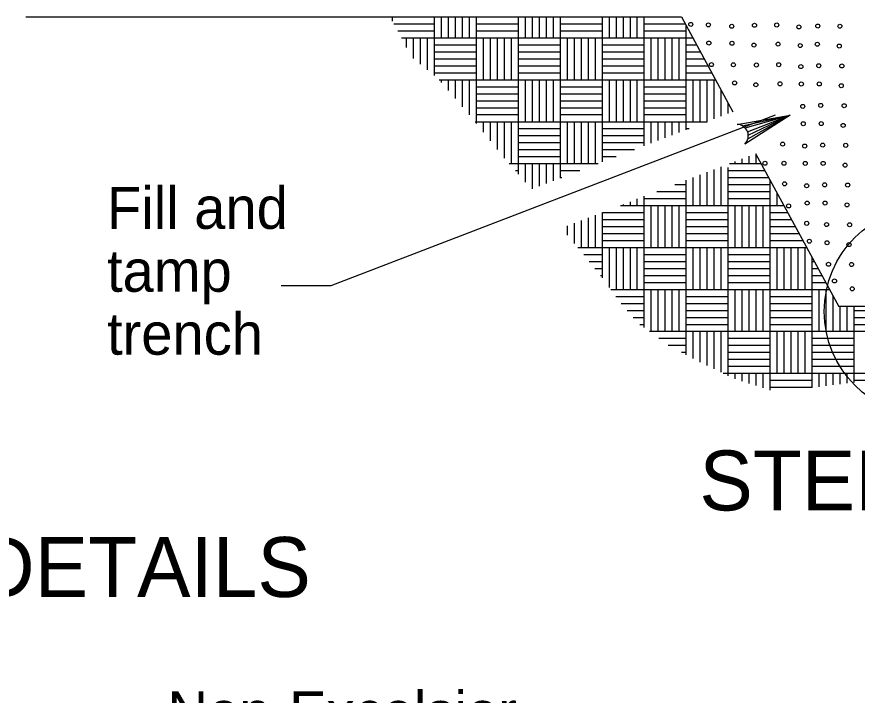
# Model space of a CAD drawing. Extents: x 1083.1 to 1117.1, y 719.4 to 741.4.
# Drawn here: x 1104.489 to 1107.293, y 732.693 to 734.956 of the extents above; entities that cross this region are included whole.
import ezdxf

# ---------------------------------------------------------------- set-up
doc = ezdxf.new("R2010")
doc.units = 0
doc.layers.add('ST_Details', color=7, linetype='Continuous')
doc.layers.add('ST_Text', color=7, linetype='Continuous')

msp = doc.modelspace()

# ---------------------------------------------------------------- linework, layer by layer
at = {"layer": 'ST_Details'}
for p, q in [((1104.5193, 734.9563), (1106.6565, 734.9563)), ((1105.7431, 734.9412), (1105.7431, 734.9563)), ((1105.7431, 734.9563), (1105.883, 734.9563)), ((1105.883, 734.7605), (1105.883, 734.9563)), ((1105.9064, 734.8863), (1105.9064, 734.9563)), ((1105.9297, 734.8863), (1105.9297, 734.9563)), ((1105.953, 734.8863), (1105.953, 734.9563)), ((1105.9764, 734.8863), (1105.9764, 734.9563)), ((1105.9997, 734.8863), (1105.9997, 734.9563)), ((1106.023, 734.6003), (1106.023, 734.9563)), ((1106.023, 734.9563), (1106.163, 734.9563)), ((1106.163, 734.4314), (1106.163, 734.9563)), ((1106.1863, 734.8863), (1106.1863, 734.9563)), ((1106.2095, 734.8863), (1106.2095, 734.9563)), ((1106.2329, 734.8863), (1106.2329, 734.9563)), ((1106.2562, 734.8863), (1106.2562, 734.9563)), ((1106.2795, 734.8863), (1106.2795, 734.9563)), ((1106.3029, 734.9563), (1106.4428, 734.9563)), ((1106.3029, 734.4184), (1106.3029, 734.9563)), ((1106.4428, 734.4721), (1106.4428, 734.9563)), ((1106.4661, 734.8863), (1106.4661, 734.9563)), ((1106.4895, 734.8863), (1106.4895, 734.9563)), ((1106.5128, 734.8863), (1106.5128, 734.9563)), ((1106.5361, 734.8863), (1106.5361, 734.9563)), ((1106.5594, 734.8863), (1106.5594, 734.9563)), ((1106.5827, 734.9563), (1106.7065, 734.9563)), ((1106.5827, 734.5259), (1106.5827, 734.9563)), ((1106.7065, 734.9563), (1106.8785, 734.6394)), ((1105.7475, 734.9329), (1105.883, 734.9329)), ((1106.023, 734.9329), (1106.163, 734.9329)), ((1106.3029, 734.9329), (1106.4428, 734.9329)), ((1106.5827, 734.9329), (1106.7191, 734.9329)), ((1105.76, 734.9096), (1105.883, 734.9096)), ((1106.023, 734.9096), (1106.163, 734.9096)), ((1106.3029, 734.9096), (1106.4428, 734.9096)), ((1106.5827, 734.9096), (1106.7227, 734.9096)), ((1106.7227, 734.5795), (1106.7227, 734.9264)), ((1105.7725, 734.8863), (1106.7444, 734.8863)), ((1105.7898, 734.8542), (1105.7898, 734.8863)), ((1105.8131, 734.8175), (1105.8131, 734.8863)), ((1105.8365, 734.7985), (1105.8365, 734.8863)), ((1105.8597, 734.7795), (1105.8597, 734.8863)), ((1106.0463, 734.7464), (1106.0463, 734.8863)), ((1106.0696, 734.7464), (1106.0696, 734.8863)), ((1106.093, 734.7464), (1106.093, 734.8863)), ((1106.1163, 734.7464), (1106.1163, 734.8863)), ((1106.1396, 734.7464), (1106.1396, 734.8863)), ((1106.3262, 734.7464), (1106.3262, 734.8863)), ((1106.3495, 734.7464), (1106.3495, 734.8863)), ((1106.3728, 734.7464), (1106.3728, 734.8863)), ((1106.3961, 734.7464), (1106.3961, 734.8863)), ((1106.4195, 734.7464), (1106.4195, 734.8863)), ((1106.606, 734.7464), (1106.606, 734.8863)), ((1106.6294, 734.7464), (1106.6294, 734.8863)), ((1106.6527, 734.7464), (1106.6527, 734.8863)), ((1106.676, 734.7464), (1106.676, 734.8863)), ((1106.6994, 734.7464), (1106.6994, 734.8863)), ((1105.883, 734.8629), (1105.953, 734.8629)), ((1105.953, 734.8629), (1106.023, 734.8629)), ((1106.163, 734.8629), (1106.2329, 734.8629)), ((1106.2329, 734.8629), (1106.3029, 734.8629)), ((1106.4428, 734.8629), (1106.5128, 734.8629)), ((1106.5128, 734.8629), (1106.5827, 734.8629)), ((1106.7227, 734.8629), (1106.757, 734.8629)), ((1105.883, 734.8397), (1105.953, 734.8397)), ((1105.883, 734.8164), (1105.953, 734.8164)), ((1105.953, 734.8397), (1106.023, 734.8397)), ((1105.953, 734.8164), (1106.023, 734.8164)), ((1106.163, 734.8397), (1106.2329, 734.8397)), ((1106.163, 734.8164), (1106.2329, 734.8164)), ((1106.2329, 734.8397), (1106.3029, 734.8397)), ((1106.2329, 734.8164), (1106.3029, 734.8164)), ((1106.4428, 734.8397), (1106.5128, 734.8397)), ((1106.4428, 734.8164), (1106.5128, 734.8164)), ((1106.5128, 734.8397), (1106.5827, 734.8397)), ((1106.5128, 734.8164), (1106.5827, 734.8164)), ((1106.7227, 734.8397), (1106.7697, 734.8397)), ((1106.7227, 734.8164), (1106.7824, 734.8164)), ((1105.883, 734.793), (1105.953, 734.793)), ((1105.953, 734.793), (1106.023, 734.793)), ((1106.163, 734.793), (1106.2329, 734.793)), ((1106.2329, 734.793), (1106.3029, 734.793)), ((1106.4428, 734.793), (1106.5128, 734.793)), ((1106.5128, 734.793), (1106.5827, 734.793)), ((1106.7227, 734.793), (1106.7926, 734.793)), ((1106.7926, 734.793), (1106.795, 734.793)), ((1105.883, 734.7697), (1105.953, 734.7697)), ((1105.953, 734.7697), (1106.023, 734.7697)), ((1106.163, 734.7697), (1106.2329, 734.7697)), ((1106.2329, 734.7697), (1106.3029, 734.7697)), ((1106.4428, 734.7697), (1106.5128, 734.7697)), ((1106.5128, 734.7697), (1106.5827, 734.7697)), ((1106.7227, 734.7697), (1106.7926, 734.7697)), ((1106.7926, 734.7697), (1106.8077, 734.7697)), ((1105.8987, 734.7464), (1106.8204, 734.7464)), ((1105.9064, 734.7374), (1105.9064, 734.7464)), ((1105.9297, 734.7104), (1105.9297, 734.7464)), ((1105.953, 734.6834), (1105.953, 734.7464)), ((1105.9764, 734.6764), (1105.9764, 734.7464)), ((1105.9997, 734.6764), (1105.9997, 734.7464)), ((1106.1863, 734.6764), (1106.1863, 734.7464)), ((1106.2095, 734.6764), (1106.2095, 734.7464)), ((1106.2329, 734.6764), (1106.2329, 734.7464)), ((1106.2562, 734.6764), (1106.2562, 734.7464)), ((1106.2795, 734.6764), (1106.2795, 734.7464)), ((1106.4661, 734.6764), (1106.4661, 734.7464)), ((1106.4895, 734.6764), (1106.4895, 734.7464)), ((1106.5128, 734.6764), (1106.5128, 734.7464)), ((1106.5361, 734.6764), (1106.5361, 734.7464)), ((1106.5594, 734.6764), (1106.5594, 734.7464)), ((1106.746, 734.6764), (1106.746, 734.7464)), ((1106.7693, 734.6064), (1106.7693, 734.7464)), ((1106.7926, 734.6064), (1106.7926, 734.7464)), ((1106.816, 734.6154), (1106.816, 734.7464)), ((1106.023, 734.723), (1106.163, 734.723)), ((1106.3029, 734.723), (1106.4428, 734.723)), ((1106.5827, 734.723), (1106.7227, 734.723)), ((1106.8393, 734.6764), (1106.8393, 734.7115)), ((1105.9764, 734.6564), (1105.9764, 734.6764)), ((1105.9997, 734.6292), (1105.9997, 734.6764)), ((1106.023, 734.6998), (1106.163, 734.6998)), ((1106.023, 734.6764), (1106.163, 734.6764)), ((1106.1863, 734.6064), (1106.1863, 734.6764)), ((1106.2095, 734.6064), (1106.2095, 734.6764)), ((1106.2329, 734.6064), (1106.2329, 734.6764)), ((1106.2562, 734.6064), (1106.2562, 734.6764)), ((1106.2795, 734.6064), (1106.2795, 734.6764)), ((1106.3029, 734.6998), (1106.4428, 734.6998)), ((1106.3029, 734.6764), (1106.4428, 734.6764)), ((1106.4661, 734.6064), (1106.4661, 734.6764)), ((1106.4895, 734.6064), (1106.4895, 734.6764)), ((1106.5128, 734.6064), (1106.5128, 734.6764)), ((1106.5361, 734.6064), (1106.5361, 734.6764)), ((1106.5594, 734.6064), (1106.5594, 734.6764)), ((1106.5827, 734.6998), (1106.7227, 734.6998)), ((1106.5827, 734.6764), (1106.7227, 734.6764)), ((1106.746, 734.6064), (1106.746, 734.6764)), ((1106.7693, 734.6624), (1106.7693, 734.6764)), ((1106.7926, 734.668), (1106.7926, 734.6764)), ((1106.816, 734.6724), (1106.816, 734.6764)), ((1106.8393, 734.6244), (1106.8393, 734.6764)), ((1106.023, 734.6531), (1106.163, 734.6531)), ((1106.3029, 734.6531), (1106.4428, 734.6531)), ((1106.5827, 734.6531), (1106.7227, 734.6531)), ((1106.8626, 734.6333), (1106.8626, 734.6686)), ((1106.023, 734.6298), (1106.163, 734.6298)), ((1106.3029, 734.6298), (1106.4428, 734.6298)), ((1106.5827, 734.6298), (1106.7227, 734.6298)), ((1106.9096, 734.5929), (1107.0697, 734.6286)), ((1106.9191, 734.5854), (1107.0697, 734.6286)), ((1106.927, 734.573), (1107.0697, 734.6286)), ((1106.9285, 734.5496), (1107.0697, 734.6286)), ((1106.9295, 734.5619), (1107.0697, 734.6286)), ((1106.018, 734.6064), (1106.7927, 734.6064)), ((1106.0463, 734.5714), (1106.0463, 734.6064)), ((1106.0696, 734.5425), (1106.0696, 734.6064)), ((1106.093, 734.5136), (1106.093, 734.6064)), ((1106.1163, 734.4849), (1106.1163, 734.6064)), ((1106.1396, 734.4665), (1106.1396, 734.6064)), ((1106.3262, 734.4665), (1106.3262, 734.6064)), ((1106.3495, 734.4665), (1106.3495, 734.6064)), ((1106.3728, 734.4665), (1106.3728, 734.6064)), ((1106.3961, 734.4665), (1106.3961, 734.6064)), ((1106.4195, 734.4665), (1106.4195, 734.6064)), ((1106.606, 734.5348), (1106.606, 734.6064)), ((1106.6294, 734.5437), (1106.6294, 734.6064)), ((1106.6527, 734.5527), (1106.6527, 734.6064)), ((1106.676, 734.5616), (1106.676, 734.6064)), ((1106.6994, 734.5706), (1106.6994, 734.6064)), ((1106.163, 734.5831), (1106.2329, 734.5831)), ((1106.2329, 734.5831), (1106.3029, 734.5831)), ((1106.4428, 734.5831), (1106.5128, 734.5831)), ((1106.5128, 734.5831), (1106.5827, 734.5831)), ((1106.7227, 734.5831), (1106.732, 734.5831)), ((1106.163, 734.5599), (1106.2329, 734.5599)), ((1106.163, 734.5365), (1106.2329, 734.5365)), ((1106.2329, 734.5599), (1106.3029, 734.5599)), ((1106.2329, 734.5365), (1106.3029, 734.5365)), ((1106.4428, 734.5599), (1106.5827, 734.5599)), ((1106.4428, 734.5365), (1106.5827, 734.5365)), ((1106.5128, 734.5599), (1106.5172, 734.5599)), ((1106.163, 734.5132), (1106.2329, 734.5132)), ((1106.2329, 734.5132), (1106.3029, 734.5132)), ((1106.4428, 734.5132), (1106.5498, 734.5132)), ((1106.163, 734.4899), (1106.2329, 734.4899)), ((1106.2329, 734.4899), (1106.3029, 734.4899)), ((1106.4428, 734.4899), (1106.4891, 734.4899)), ((1106.9092, 734.4665), (1106.9092, 734.4827)), ((1106.9325, 734.4665), (1106.9325, 734.4917)), ((1106.9541, 734.4999), (1107.2312, 733.9896)), ((1106.9559, 734.4665), (1106.9559, 734.4968)), ((1106.1323, 734.4665), (1106.4284, 734.4665)), ((1106.1863, 734.4048), (1106.1863, 734.4665)), ((1106.2095, 734.3825), (1106.2095, 734.4665)), ((1106.2329, 734.3914), (1106.2329, 734.4665)), ((1106.2562, 734.4004), (1106.2562, 734.4665)), ((1106.2795, 734.4094), (1106.2795, 734.4665)), ((1106.8393, 734.3966), (1106.8393, 734.4559)), ((1106.8626, 733.7589), (1106.8626, 734.4535)), ((1106.8672, 734.4665), (1106.9723, 734.4665)), ((1106.886, 734.4665), (1106.886, 734.4738)), ((1106.1527, 734.4432), (1106.163, 734.4432)), ((1106.3029, 734.4432), (1106.3677, 734.4432)), ((1106.7693, 734.3966), (1106.7693, 734.4289)), ((1106.7926, 734.3966), (1106.7926, 734.4379)), ((1106.816, 734.3966), (1106.816, 734.4469)), ((1106.8626, 734.4432), (1106.985, 734.4432)), ((1106.3029, 734.4199), (1106.307, 734.4199)), ((1106.685, 734.3966), (1106.7227, 734.3966)), ((1106.7227, 733.8284), (1106.7227, 734.411)), ((1106.746, 734.3966), (1106.746, 734.42)), ((1106.746, 734.3266), (1106.746, 734.3966)), ((1106.7693, 734.3266), (1106.7693, 734.3966)), ((1106.7926, 734.3266), (1106.7926, 734.3966)), ((1106.816, 734.3266), (1106.816, 734.3966)), ((1106.8393, 734.3266), (1106.8393, 734.3966)), ((1106.8626, 734.4199), (1106.9976, 734.4199)), ((1106.8626, 734.3966), (1107.0025, 734.3966)), ((1107.0025, 733.7108), (1107.0025, 734.4109)), ((1106.6244, 734.3733), (1106.7227, 734.3733)), ((1106.8626, 734.3733), (1107.0025, 734.3733)), ((1107.0259, 734.3266), (1107.0259, 734.3679)), ((1106.5361, 734.3266), (1106.5361, 734.3394)), ((1106.5594, 734.3266), (1106.5594, 734.3484)), ((1106.5827, 733.9193), (1106.5827, 734.3573)), ((1106.5827, 734.3499), (1106.7227, 734.3499)), ((1106.8626, 734.3499), (1107.0025, 734.3499)), ((1106.5029, 734.3266), (1107.0483, 734.3266)), ((1106.5128, 734.3266), (1106.5128, 734.3304)), ((1106.606, 734.1867), (1106.606, 734.3266)), ((1106.6294, 734.1867), (1106.6294, 734.3266)), ((1106.6527, 734.1867), (1106.6527, 734.3266)), ((1106.676, 734.1867), (1106.676, 734.3266)), ((1106.6994, 734.1867), (1106.6994, 734.3266)), ((1106.886, 734.1867), (1106.886, 734.3266)), ((1106.9092, 734.1867), (1106.9092, 734.3266)), ((1106.9325, 734.1867), (1106.9325, 734.3266)), ((1106.9559, 734.1867), (1106.9559, 734.3266)), ((1106.9792, 734.1867), (1106.9792, 734.3266)), ((1106.3961, 734.1867), (1106.3961, 734.2856)), ((1106.4195, 734.1867), (1106.4195, 734.2946)), ((1106.4428, 734.0852), (1106.4428, 734.3035)), ((1106.4428, 734.3033), (1106.5128, 734.3033)), ((1106.5128, 734.3033), (1106.5827, 734.3033)), ((1106.7227, 734.3033), (1106.7926, 734.3033)), ((1106.7926, 734.3033), (1106.8626, 734.3033)), ((1107.0025, 734.3033), (1107.061, 734.3033)), ((1106.3262, 734.2281), (1106.3262, 734.2588)), ((1106.3495, 734.1998), (1106.3495, 734.2677)), ((1106.3728, 734.1867), (1106.3728, 734.2767)), ((1106.4428, 734.2799), (1106.5128, 734.2799)), ((1106.4428, 734.2567), (1106.5128, 734.2567)), ((1106.5128, 734.2799), (1106.5827, 734.2799)), ((1106.5128, 734.2567), (1106.5827, 734.2567)), ((1106.7227, 734.2799), (1106.7926, 734.2799)), ((1106.7227, 734.2567), (1106.7926, 734.2567)), ((1106.7926, 734.2799), (1106.8626, 734.2799)), ((1106.7926, 734.2567), (1106.8626, 734.2567)), ((1107.0025, 734.2799), (1107.0725, 734.2799)), ((1107.0025, 734.2567), (1107.0725, 734.2567)), ((1107.0725, 734.2799), (1107.0736, 734.2799)), ((1107.0725, 734.2567), (1107.0862, 734.2567)), ((1106.4428, 734.2334), (1106.5128, 734.2334)), ((1106.5128, 734.2334), (1106.5827, 734.2334)), ((1106.7227, 734.2334), (1106.7926, 734.2334)), ((1106.7926, 734.2334), (1106.8626, 734.2334)), ((1107.0025, 734.2334), (1107.0725, 734.2334)), ((1107.0725, 734.2334), (1107.0989, 734.2334)), ((1106.4428, 734.21), (1106.5128, 734.21)), ((1106.5128, 734.21), (1106.5827, 734.21)), ((1106.7227, 734.21), (1106.7926, 734.21)), ((1106.7926, 734.21), (1106.8626, 734.21)), ((1107.0025, 734.21), (1107.0725, 734.21)), ((1107.0725, 734.21), (1107.1115, 734.21)), ((1106.361, 734.1867), (1107.1242, 734.1867)), ((1106.4661, 734.1168), (1106.4661, 734.1867)), ((1106.4895, 734.1168), (1106.4895, 734.1867)), ((1106.5128, 734.1168), (1106.5128, 734.1867)), ((1106.5361, 734.1168), (1106.5361, 734.1867)), ((1106.5594, 734.1168), (1106.5594, 734.1867)), ((1106.746, 734.1168), (1106.746, 734.1867)), ((1106.7693, 734.1168), (1106.7693, 734.1867)), ((1106.7926, 734.1168), (1106.7926, 734.1867)), ((1106.816, 734.1168), (1106.816, 734.1867)), ((1106.8393, 734.1168), (1106.8393, 734.1867)), ((1107.0259, 734.1168), (1107.0259, 734.1867)), ((1107.0492, 734.1168), (1107.0492, 734.1867)), ((1107.0725, 734.1168), (1107.0725, 734.1867)), ((1107.0958, 734.1168), (1107.0958, 734.1867)), ((1107.1191, 734.1168), (1107.1191, 734.1867)), ((1106.3806, 734.1634), (1106.4428, 734.1634)), ((1106.5827, 734.1634), (1106.7227, 734.1634)), ((1106.8626, 734.1634), (1107.0025, 734.1634)), ((1107.1425, 733.7192), (1107.1425, 734.153)), ((1106.3992, 734.14), (1106.4428, 734.14)), ((1106.4179, 734.1168), (1106.4428, 734.1168)), ((1106.4661, 734.0534), (1106.4661, 734.1168)), ((1106.4895, 734.0468), (1106.4895, 734.1168)), ((1106.5128, 734.0468), (1106.5128, 734.1168)), ((1106.5361, 734.0468), (1106.5361, 734.1168)), ((1106.5594, 734.0468), (1106.5594, 734.1168)), ((1106.5827, 734.14), (1106.7227, 734.14)), ((1106.5827, 734.1168), (1106.7227, 734.1168)), ((1106.746, 734.0468), (1106.746, 734.1168)), ((1106.7693, 734.0468), (1106.7693, 734.1168)), ((1106.7926, 734.0468), (1106.7926, 734.1168)), ((1106.816, 734.0468), (1106.816, 734.1168)), ((1106.8393, 734.0468), (1106.8393, 734.1168)), ((1106.8626, 734.14), (1107.0025, 734.14)), ((1106.8626, 734.1168), (1107.0025, 734.1168)), ((1107.0259, 734.0468), (1107.0259, 734.1168)), ((1107.0492, 734.0468), (1107.0492, 734.1168)), ((1107.0725, 734.0468), (1107.0725, 734.1168)), ((1107.0958, 734.0468), (1107.0958, 734.1168)), ((1107.1191, 734.0468), (1107.1191, 734.1168)), ((1107.1425, 734.14), (1107.1495, 734.14)), ((1107.1425, 734.1168), (1107.1622, 734.1168)), ((1106.4365, 734.0934), (1106.4428, 734.0934)), ((1106.5827, 734.0934), (1106.7227, 734.0934)), ((1106.8626, 734.0934), (1107.0025, 734.0934)), ((1107.1425, 734.0934), (1107.1749, 734.0934)), ((1106.5827, 734.0701), (1106.7227, 734.0701)), ((1106.8626, 734.0701), (1107.0025, 734.0701)), ((1107.1425, 734.0701), (1107.1875, 734.0701)), ((1106.471, 734.0468), (1107.2002, 734.0468)), ((1106.606, 733.9069), (1106.606, 734.0468)), ((1106.6294, 733.9069), (1106.6294, 734.0468)), ((1106.6527, 733.9069), (1106.6527, 734.0468)), ((1106.676, 733.9069), (1106.676, 734.0468)), ((1106.6994, 733.9069), (1106.6994, 734.0468)), ((1106.886, 733.9069), (1106.886, 734.0468)), ((1106.9092, 733.9069), (1106.9092, 734.0468)), ((1106.9325, 733.9069), (1106.9325, 734.0468)), ((1106.9559, 733.9069), (1106.9559, 734.0468)), ((1106.9792, 733.9069), (1106.9792, 734.0468)), ((1107.1658, 733.9069), (1107.1658, 734.0468)), ((1107.1891, 733.9069), (1107.1891, 734.0468)), ((1106.488, 734.0234), (1106.5128, 734.0234)), ((1106.5128, 734.0234), (1106.5827, 734.0234)), ((1106.7227, 734.0234), (1106.7926, 734.0234)), ((1106.7926, 734.0234), (1106.8626, 734.0234)), ((1107.0025, 734.0234), (1107.0725, 734.0234)), ((1107.0725, 734.0234), (1107.1425, 734.0234)), ((1107.2125, 733.9069), (1107.2125, 734.0242)), ((1106.5059, 734.0001), (1106.5128, 734.0001)), ((1106.5128, 734.0001), (1106.5827, 734.0001)), ((1106.5256, 733.9769), (1106.5827, 733.9769)), ((1106.7227, 734.0001), (1106.7926, 734.0001)), ((1106.7227, 733.9769), (1106.7926, 733.9769)), ((1106.7926, 734.0001), (1106.8626, 734.0001)), ((1106.7926, 733.9769), (1106.8626, 733.9769)), ((1107.0025, 734.0001), (1107.0725, 734.0001)), ((1107.0025, 733.9769), (1107.0725, 733.9769)), ((1107.0725, 734.0001), (1107.1425, 734.0001)), ((1107.0725, 733.9769), (1107.1425, 733.9769)), ((1107.5895, 733.9896), (1107.2312, 733.9896)), ((1107.2358, 733.9069), (1107.2358, 733.9896)), ((1107.2591, 733.9069), (1107.2591, 733.9896)), ((1107.2824, 733.7364), (1107.2824, 733.9896)), ((1107.2824, 733.9769), (1107.3524, 733.9769)), ((1106.5453, 733.9535), (1106.5827, 733.9535)), ((1106.7227, 733.9535), (1106.7926, 733.9535)), ((1106.7926, 733.9535), (1106.8626, 733.9535)), ((1107.0025, 733.9535), (1107.0725, 733.9535)), ((1107.0725, 733.9535), (1107.1425, 733.9535)), ((1107.2824, 733.9535), (1107.3524, 733.9535)), ((1106.5679, 733.9302), (1106.5827, 733.9302)), ((1106.7227, 733.9302), (1106.7926, 733.9302)), ((1106.7926, 733.9302), (1106.8626, 733.9302)), ((1107.0025, 733.9302), (1107.0725, 733.9302)), ((1107.0725, 733.9302), (1107.1425, 733.9302)), ((1107.2824, 733.9302), (1107.3524, 733.9302)), ((1106.5995, 733.9069), (1107.5895, 733.9069)), ((1106.746, 733.8369), (1106.746, 733.9069)), ((1106.7693, 733.8369), (1106.7693, 733.9069)), ((1106.7926, 733.8369), (1106.7926, 733.9069)), ((1106.816, 733.8369), (1106.816, 733.9069)), ((1106.8393, 733.8369), (1106.8393, 733.9069)), ((1107.0259, 733.8369), (1107.0259, 733.9069)), ((1107.0492, 733.8369), (1107.0492, 733.9069)), ((1107.0725, 733.8369), (1107.0725, 733.9069)), ((1107.0958, 733.8369), (1107.0958, 733.9069)), ((1107.1191, 733.8369), (1107.1191, 733.9069)), ((1106.6311, 733.8835), (1106.7227, 733.8835)), ((1106.8626, 733.8835), (1107.0025, 733.8835)), ((1107.1425, 733.8835), (1107.2824, 733.8835)), ((1106.6628, 733.8602), (1106.7227, 733.8602)), ((1106.7064, 733.8369), (1106.7227, 733.8369)), ((1106.746, 733.8161), (1106.746, 733.8369)), ((1106.7693, 733.8039), (1106.7693, 733.8369)), ((1106.7926, 733.7923), (1106.7926, 733.8369)), ((1106.816, 733.7812), (1106.816, 733.8369)), ((1106.8393, 733.7701), (1106.8393, 733.8369)), ((1106.8626, 733.8602), (1107.0025, 733.8602)), ((1106.8626, 733.8369), (1107.0025, 733.8369)), ((1107.0259, 733.7669), (1107.0259, 733.8369)), ((1107.0492, 733.7669), (1107.0492, 733.8369)), ((1107.0725, 733.7669), (1107.0725, 733.8369)), ((1107.0958, 733.7669), (1107.0958, 733.8369)), ((1107.1191, 733.7669), (1107.1191, 733.8369)), ((1107.1425, 733.8602), (1107.2824, 733.8602)), ((1107.1425, 733.8369), (1107.2824, 733.8369)), ((1106.8626, 733.8136), (1107.0025, 733.8136)), ((1107.1425, 733.8136), (1107.2824, 733.8136)), ((1106.8626, 733.7903), (1107.0025, 733.7903)), ((1107.1425, 733.7903), (1107.2824, 733.7903)), ((1106.846, 733.7669), (1107.5895, 733.7669)), ((1106.886, 733.7482), (1106.886, 733.7669)), ((1106.9092, 733.7407), (1106.9092, 733.7669)), ((1106.9325, 733.7332), (1106.9325, 733.7669)), ((1106.9559, 733.7258), (1106.9559, 733.7669)), ((1106.9792, 733.7183), (1106.9792, 733.7669)), ((1107.1658, 733.722), (1107.1658, 733.7669)), ((1107.1891, 733.7249), (1107.1891, 733.7669)), ((1107.2125, 733.7278), (1107.2125, 733.7669)), ((1107.2358, 733.7306), (1107.2358, 733.7669)), ((1107.2591, 733.7335), (1107.2591, 733.7669)), ((1107.0025, 733.7436), (1107.0725, 733.7436)), ((1107.0725, 733.7436), (1107.1425, 733.7436)), ((1107.2824, 733.7436), (1107.3524, 733.7436)), ((1107.0025, 733.7203), (1107.0725, 733.7203)), ((1107.0725, 733.7203), (1107.1425, 733.7203))]:
    msp.add_line(p, q, dxfattribs=at)
for points in [[(1107.0197, 734.6286), (1105.537, 734.0591), (1105.3715, 734.0591)], [(1106.892, 734.5974), (1107.0697, 734.6286), (1106.9176, 734.5314)]]:
    msp.add_lwpolyline(points, dxfattribs=at)
msp.add_circle((1107.5319, 733.9733), 0.3487, dxfattribs=at)
msp.add_arc((1106.8915, 734.5592), 0.0382, 313.3584, 89.1846, dxfattribs=at)
for centre in [(1106.7378, 734.9311), (1106.7964, 734.9294), (1106.8745, 734.9247), (1106.9503, 734.928), (1107.0246, 734.929), (1107.0984, 734.9225), (1107.1615, 734.9253), (1107.2353, 734.9249), (1106.798, 734.8686), (1106.875, 734.8679), (1107.0291, 734.8651), (1107.16, 734.8648), (1106.9483, 734.8619), (1107.1028, 734.8604), (1107.2333, 734.8588), (1106.8068, 734.7969), (1106.8798, 734.7962), (1106.9568, 734.7955), (1107.0311, 734.7965), (1107.1049, 734.79), (1107.1648, 734.7931), (1107.2418, 734.7924), (1106.8838, 734.7356), (1106.9548, 734.7294), (1107.0356, 734.7326), (1107.1066, 734.7321), (1107.1665, 734.7323), (1107.2398, 734.7263), (1107.1114, 734.6575), (1107.1713, 734.6606), (1107.2496, 734.6597), (1107.1131, 734.5996), (1107.1729, 734.5998), (1107.2462, 734.5938), (1107.0441, 734.5315), (1107.1778, 734.5281), (1107.2547, 734.5274), (1107.1179, 734.525), (1106.9852, 734.4676), (1107.0486, 734.4676), (1107.1196, 734.4671), (1107.1794, 734.4673), (1107.2527, 734.4613), (1107.0506, 734.399), (1107.1244, 734.3925), (1107.1843, 734.3956), (1107.2612, 734.3949), (1107.1261, 734.3346), (1107.1859, 734.3348), (1107.0641, 734.3252), (1107.2592, 734.3288), (1107.1246, 734.2672), (1107.1908, 734.2631), (1107.2677, 734.2624), (1107.1336, 734.2076), (1107.1924, 734.2023), (1107.2657, 734.1963), (1107.1973, 734.1306), (1107.2742, 734.1299), (1107.2172, 734.075), (1107.2764, 734.0487)]:
    msp.add_ellipse(centre, major_axis=(0.00673, 0), ratio=0.999895, dxfattribs=at)

# ---------------------------------------------------------------- texts
at = {"layer": 'ST_Text'}
for s, height, p in [('Fill and', 0.14, (1104.79, 734.2488)), ('tamp', 0.14, (1104.79, 734.0388)), ('trench', 0.14, (1104.79, 733.8288)), ('STEP 2', 0.2, (1106.7664, 733.3092)), ('CHECK SLOT CONSTRUCTION DETAILS', 0.2, (1100.3435, 733.0205)), ('Non-Excelsior', 0.14, (1104.992, 732.566))]:
    msp.add_text(s, height=height, dxfattribs=at).set_placement(p)

doc.saveas('drawing.dxf')
